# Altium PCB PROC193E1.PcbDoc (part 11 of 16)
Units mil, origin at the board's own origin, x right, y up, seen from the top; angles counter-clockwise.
Board outline 7700 x 2300 mil, 6 copper layers (Top Layer, GND 1, SIG 1, PWR, GND 2, Bottom Layer), stack 60.98 mil thick; 946 components, 667 nets, 9401 pads, 1730 vias.
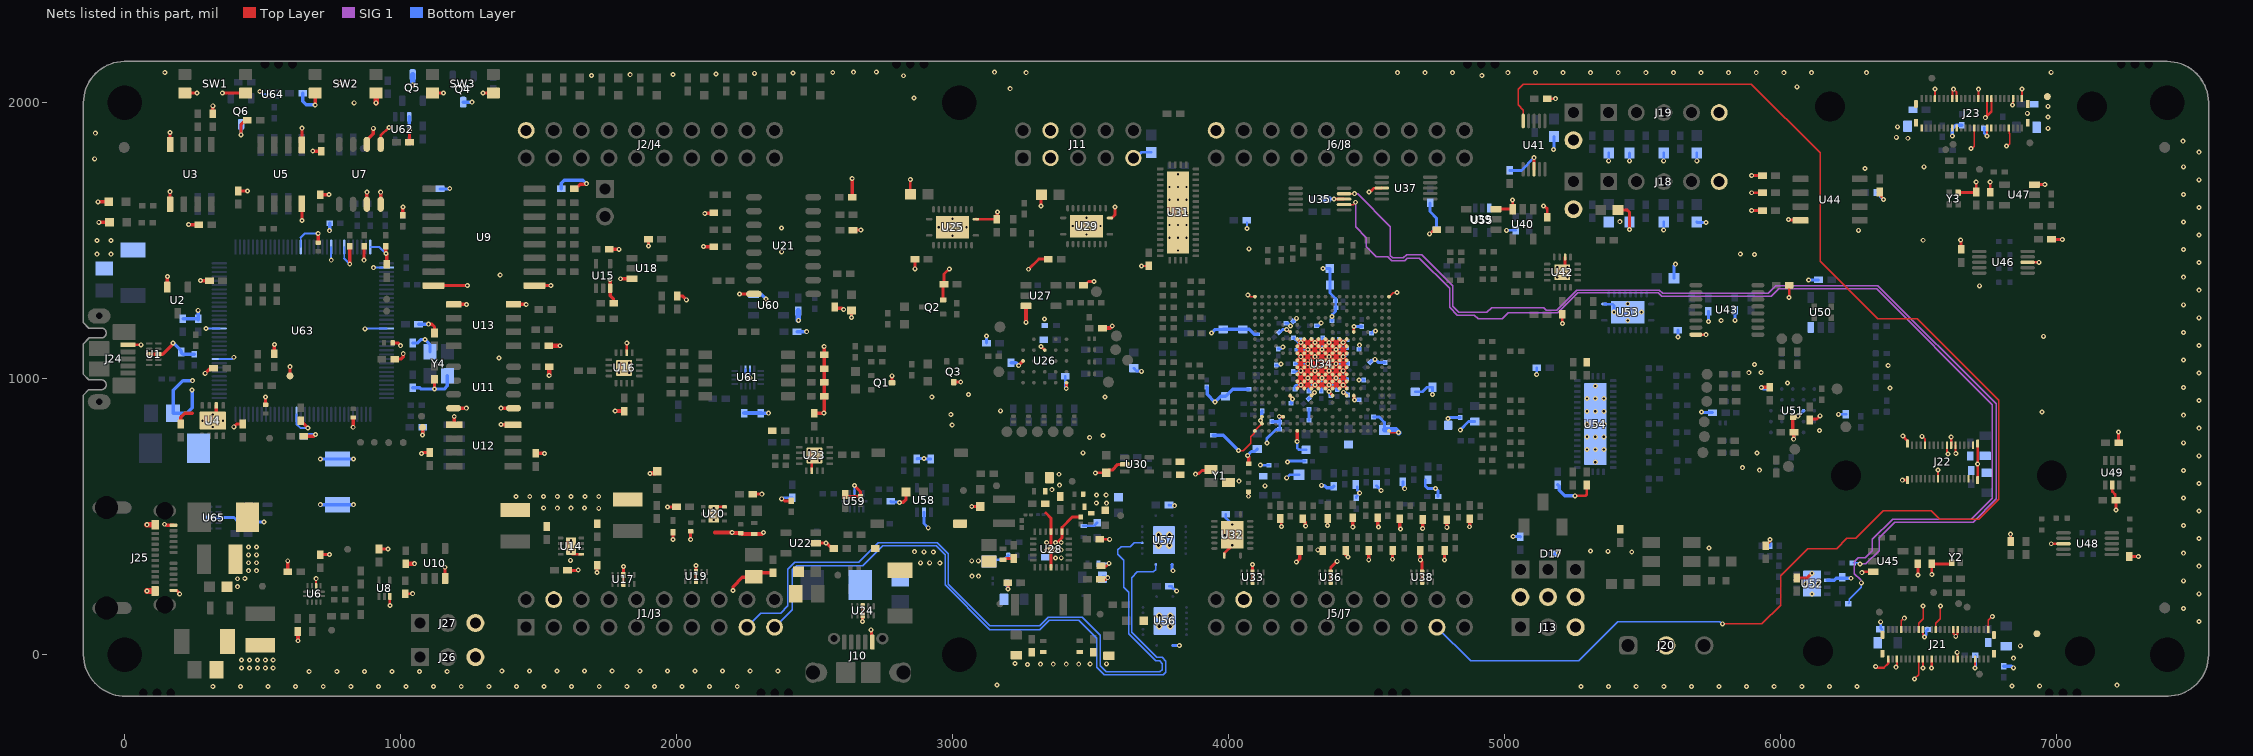
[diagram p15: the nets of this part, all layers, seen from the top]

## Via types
v1: diameter 18, hole 8, Top Layer to Bottom Layer, tented both sides, 1710 vias
v2: diameter 18, hole 8, Top Layer to Bottom Layer, tented top, 12 vias
v3: diameter 23.62, hole 11.81, Top Layer to Bottom Layer, tented both sides, 8 vias

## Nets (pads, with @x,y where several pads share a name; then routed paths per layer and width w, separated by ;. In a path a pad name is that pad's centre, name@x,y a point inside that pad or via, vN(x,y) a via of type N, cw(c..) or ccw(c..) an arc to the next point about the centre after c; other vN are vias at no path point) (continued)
GND: C1.1 C4.2 C5.2 C8.1 C11.2 C12.2 C15.2 C20.2 C22.2 C26.1 C27.2 C31.2 C32.1 C33.1 C34.2 C35.2 C36.2 C37.1 C38.2 C39.2 C40.2 C41.2 C42.1 C43.1 C44.2 C45.1 C46.1 C47.2 C48.2 C49.1 C50.2 C51.2 C52.2 C53.2 C54.1 C55.1 C56.2 C57.1 C58.2 C59.1 C60.2 C61.2 C62.2 C63.2 C64.2 C66.2 C67.2 C68.2 C69.2 C70.2 C71.2 C72.1 C73.2 C74.2 C75.2 C76.2 C77.2 C78.2 C79.2 C80.2 C81.2 C82.2 C83.2 C84.1 C85.2 C86.1 C87.2 C88.1 C89.1 C90.1 C91.1 C92.1 C93.1 C94.1 C95.1 C96.1 C97.1 C98.1 C99.1 C100.1 C101.1 C102.1 C103.1 C104.1 C105.1 C106.1 C107.1 C108.1 C109.2 C110.2 C112.2 C114.2 C115.2 C116.1 C117.2 C118.2 C119.1 C120.2 C121.1 C122.2 C123.2 C124.1 C125.2 C126.2 C127.2 C128.1 C129.1 C130.2 C131.2 C132.2 C133.2 C134.2 C135.2 C136.2 C137.2 C138.2 C139.2 C140.2 C141.2 C142.1 C143.2 C144.2 C145.2 C146.1 C147.2 C148.2 C149.2 C150.2 C151.2 C152.2 C153.2 C154.2 C155.2 C156.2 C157.2 C158.1 C159.2 C160.1 C161.1 C162.1 C163.1 C164.1 C165.1 C167.1 C168.2 C169.2 C170.1 C171.2 C172.2 C173.2 C174.2 C175.2 C176.2 C177.2 C178.1 C179.2 C180.1 C181.1 C182.1 C183.1 C184.1 C185.1 C186.2 C187.1 C188.1 C189.1 C190.2 C191.2 C192.2 C193.2 C194.1 C195.1 C196.1 C197.2 C198.1 C200.2 C201.2 C202.2 C203.2 C204.2 C205.2 C206.1 C207.2 C208.1 C209.2 C210.2 C211.2 C212.1 C213.2 C214.2 C215.2 C216.2 C217.1 C218.2 C219.2 C220.2 C221.2 C222.2 C223.2 C224.2 C225.2 C226.2 C227.2 C228.1 C229.1 C230.2 C231.1 C232.1 C233.1 C234.1 C235.1 C236.2 C237.2 C238.1 C239.2 C240.1 C241.1 C242.2 C243.1 C244.2 C245.2 C246.2 C247.2 C248.2 C249.2 C250.2 C251.2 C252.2 C253.2 C254.2 C255.2 C256.1 C257.1 C258.1 C264.2 C266.1 D2.1 D7.1 D12.1 D14.1 D15.1 D16.1 D17.2 D18.1 J1/J3.22 J2/J4.20 J5/J7.62 J6/J8.60 J10.5 J11.3 J11.4 J11.9 J12.2 J13.3 J14.2 J15.2 J16.2 J17.2 J18.5 J19.5 J20.2 J21.1 J21.5 J21.8 J21.15 J21.16 J21.17 J21.18 J21.21 J21.24 J21.31 J21.32 J21.33 J21.34 J21.41 J21.49 J21.50 J21.51 J21.52 J22.1 J22.4 J22.9 J22.11 J22.13 J22.18 J22.23 J22.31 J22.32 J22.33 J22.34 J23.1 J23.5 J23.8 J23.15 J23.16 J23.17 J23.18 J23.21 J23.24 J23.31 J23.32 J23.33 J23.34 J23.41 J23.49 J23.50 J23.51 J23.52 J25.A1 J25.A12 J25.B1 J25.B12 J26.3 J27.3 Q1.3 Q2.2 Q3.3 Q4.3 Q5.3 Q6.3 R3.2 R13.1 R15.1 R25.2 R31.2 R50.1 R51.2 R53.1 R55.1 R60.1 R63.2 R66.2 R68.1 R69.1 R70.1 R71.1 R72.2 R74.1 R75.1 R80.2 R85.1 R88.1 R90.2 R101.1 R121.1 R189.2 R190.2 R195.1 R200.1 R201.1 R202.1 R216.2 R218.2 R231.2 R233.1 R235.2 R236.2 R239.1 R246.2 R253.1 R264.1 R267.2 R274.2 R302.2 R303.2 R308.1 R314.1 R319.1 R323.1 R351.1 R352.2 R354.2 R362.1 R363.2 R374.1 SW1.1 SW1.3 SW2.1 SW2.3 SW3.1 SW3.3 SW5.2 TP55.1 TP56.1 U3.4 U5.5 U6.10 U7.5 U7.6 U8.3 U9.9 U10.3 U11.5 U12.4 U13.4 U14.5 U14.9 U15.3 U16.6 U16.17@1809.13,1039.54 U17.3@1806.54,256.9 U17.8@1806.54,289.78 U18.3 U19.3@2069.81,267.45 U19.8@2069.81,300.32 U20.3 U20.7@2134.1,510.44 U21.16 U22.2 U23.6 U23.17@2498.69,722.15 U24.3@2674,142.95 U24.8@2674,175.83 U25.11 U25.21 U26.B3 U26.C1 U26.E5 U27.3 U28. U28.2 U28.4 U28.16 U29.11 U29.21 U30.2 U31.43 U32.8 U32.17 U33.3@4085.92,264.9 U33.8@4085.92,297.78 U34.A1 U34.A20 U34.F6 U34.F15 U34.G7 U34.G8 U34.G9 U34.G10 U34.G11 U34.G12 U34.G13 U34.G14 U34.H7 U34.H8 U34.H9 U34.H10 U34.H11 U34.H12 U34.H13 U34.H14 U34.J7 U34.J8 U34.J9 U34.J10 U34.J11 U34.J12 U34.J13 U34.J14 U34.K7 U34.K8 U34.K9 U34.K10 U34.K11 U34.K12 U34.K13 U34.K14 U34.L7 U34.L8 U34.L9 U34.L10 U34.L11 U34.L12 U34.L13 U34.L14 U34.M7 U34.M8 U34.M9 U34.M10 U34.M11 U34.M12 U34.M13 U34.M14 U34.N7 U34.N8 U34.N9 U34.N10 U34.N11 U34.N12 U34.N13 U34.N14 U34.P7 U34.P8 U34.P9 U34.P10 U34.P11 U34.P12 U34.P13 U34.P14 U34.R6 U34.R9 U34.R12 U34.R14 U34.R15 U34.V2 U34.V5 U34.W2 U34.Y1 U34.Y7 U34.Y20 U35.3 U36.3@4369.09,297.78 U36.8@4369.09,264.9 U37.3 U38.3@4700.31,297.78 U38.8@4700.31,264.9 U39.3 U40.3 U41.3 U42.6 U42.17@5208.52,1386.21 U43.8 U44.4 U45.3 U46.3 U47.3 U48.3 U49.2 U50.3 U51.B3 U51.C1 U51.E5 U52.2 U52.9 U53.11 U53.21 U54.43 U55.3 U56.8 U56.17 U57.8 U57.17 U58.2 U59.9 U60.3 U61.10 U61.11 U62.3 U64.2 U65.3@306.02,497.27 U65.8@338.89,497.27 Y1.2 Y1.4 Y2.2 Y3.2 | length 19237.5
  Top Layer w5.3: v1(4035.17,739.99) 4052.27,739.99 4079.46,767.19 4079.46,789.53 4092.86,802.93 4092.86,809.76 U34.Y1@4094.49,811.38 U34.W2@4120.08,836.97 ; v1(4068.86,1303.93) 4072.29,1303.93 4078.62,1297.6 U34.A1@4094.49,1297.6 ; v1(4114.93,849.12) 4120.08,854.27 U34.V2@4120.08,862.57 ; v1@4415.65,950.85 v1(4415.65,951.09) ; U34.Y20@4580.71,811.38 4587.03,805.06 v1(4615.01,805.06) ; U34.A20@4580.71,1297.6 4595.69,1312.59 v1(4609.23,1312.59) ; J21.8@6436.31,91.39 6436.31,124.21 6444.68,132.59 v1(6447.51,132.59) ; v1@6483.89,-87.09 6499.3,-71.68 J21.15@6499.3,-15.3 ; J21.16@6499.3,91.39 6499.3,114.06 6515.41,130.17 v1(6515.41,176.47) ; J21.24@6562.29,91.39 6561.76,91.92 6561.76,114.13 6578.41,130.77 v1(6578.41,176.47) ; v1@6691.78,1834 6700.18,1842.4 J23.24@6700.18,1908.44 ; v1(6818,1843) 6820.55,1843 6829.07,1851.51 6829.07,1887.65 6826.86,1889.85 6826.86,1898.1 6826.17,1898.8 J23.8@6826.17,1908.44
  Top Layer w7: U6.10@693.44,250.21 v1(693.44,275.6) ; v1(6512.08,791.6) 6522.89,780.79 J22.23@6522.89,759.66 ; J22.18@6570.14,638.4 v1@6570.14,669.39 ; J22.13@6601.63,759.66 6601.63,734.57 6605.57,730.64 v1(6605.57,727.93) ; v1(6625.22,2049.35) 6637.19,2037.37 J23.31@6637.19,2015.13 ; J22.9@6633.13,759.66 6633.13,730.31 v1(6633.94,729.5)
  Top Layer w8: U16.6@1818.97,1094.65 v1(1818.97,1129.8) ; v1(2479.99,703.45) 2483.01,703.45 2488.85,697.61 U23.6@2488.85,667.03 ; v1(3683.7,1408.2) 3708.05,1408.2 C86.1@3709.11,1409.27 ; v1@4071.45,574.51 C88.1@4071.47,591.21 ; v1(6343.79,-42.49) 6348.6,-47.3 6373.06,-47.3 6389.06,-31.3 J21.1@6389.06,-15.3 ; v1(6417.83,-45.04) 6420.56,-42.31 J21.5@6420.56,-15.3 ; v1(6514.71,-47.64) 6515.05,-47.3 J21.17@6515.05,-15.3 ; J21.18@6515.05,91.39 6515.57,90.87 6515.57,73.18 6521.05,67.71 v1(6521.05,65) ; v1(6546.21,-47.64) 6546.54,-47.3 J21.21@6546.54,-15.3 ; J23.41@6558.45,2015.13 v1(6558.45,2049.91) ; J22.11@6617.38,759.66 v1(6617.38,788.61) ; J23.33@6621.44,2015.13 6621.44,2023.95 6621.62,2024.13 6621.62,2043.04 6623.3,2044.73 6623.3,2047.43 v1(6625.22,2049.35) ; J21.32@6625.28,91.39 6625.81,90.87 6625.81,76.58 v1@6633.88,68.51 ; v1(6633.88,66.89) v1@6633.88,68.51 ; v1(6639.05,9) 6640.5,7.55 6640.5,-14.77 J21.33@6641.03,-15.3 ; J21.34@6641.03,91.39 6640.5,90.87 6640.5,76.22 6633.88,69.6 v1@6633.88,68.51 ; v1(6703.69,-47.64) 6704.02,-47.3 J21.41@6704.02,-15.3 ; J23.21@6715.93,2015.13 v1(6715.93,2049.35) ; v1(6741,1946) v1@6746.91,1951.91 ; v1(6747.43,1879.92) J23.18@6747.43,1908.44 ; J23.17@6747.43,2015.13 6747.43,1960.13 6746.91,1959.62 v1@6746.91,1951.91 ; J23.15@6763.17,2015.13 6763.17,1968.17 v1@6746.91,1951.91 ; v1(6839.9,1992.32) 6841.39,1993.8 6841.39,2014.61 J23.5@6841.91,2015.13 ; J23.1@6873.41,2015.13 v1@6873.41,2050.04
  Top Layer w10: U7.5@927.09,1849.31 927.09,1881.02 v1(956.83,1910.76) ; v1@960.35,178.54 U8.3@960.35,211.46 ; R25.2@1016.9,221.53 v1(1043.03,221.53) ; C26.1@1031.48,1856.71 1031.48,1900.04 v1(1032.23,1900.79) ; U10.3@1160.43,276.85 v1(1160.43,317.22) ; R31.2@1603.84,305.62 1639,305.62 1640.73,307.35 v1(1642.89,307.35) ; v1(1616.72,372.03) 1616.72,370.06 1622.62,364.15 U14.5@1654.12,364.15 ; U14.9@1616.72,393.68 1616.72,379.9 U14.9@1620.65,375.96 ; v1(1710.81,297.92) 1711.09,298.19 1711.09,323.87 C38.2@1711.37,324.15 ; U17.3@1806.54,256.9 U17.8@1806.54,289.78 v1(1806.54,319.63) ; U19.3@2069.81,267.45 U19.8@2069.81,300.32 2069.81,323.38 v1(2070.03,323.6) ; v1(2134.1,532.09) 2138.04,536.03 U20.3@2172.49,536.03 ; v1(2703.14,90.7) 2703.14,88.53 2705.58,86.1 2705.58,49.04 J10.5@2708.45,46.17 ; Q1.3@2779.73,985.75 v1(2779.73,1010.72) ; v1(2846.02,1722.5) 2846.02,1669.97 C58.2@2847.31,1668.67 ; C59.1@2862.89,1433.48 2863.13,1433.24 v1(2863.13,1398.63) ; Q2.2@2964.69,1285.58 2964.69,1338.47 R85.1@2968.27,1342.04 2968.27,1379.35 v1(2987.21,1398.28) ; Q3.3@3003.55,988.08 v1(3028.84,988.08) ; v1(3068.61,537.33) 3099.75,537.33 D14.1@3099.79,537.37 ; U25.11@3083.62,1578.6 3145.94,1578.29 3153.27,1578.29 R90.2@3160.08,1578.29 ; C61.2@3181.83,344.4 3186.33,344.4 3191.19,349.25 C63.2@3221.59,349.25 ; C62.2@3199.08,261.73 3199.57,261.24 v1(3199.57,238.84) ; v1(3238.72,1048.62) v1@3238.72,1048.71 ; U26.C1@3254.52,1064.51 U26.C1@3254.52,1064.6 ; v1(3274.71,1396.93) 3311.69,1433.91 C72.1@3346.13,1433.91 ; v1(3319.1,1626.17) 3319.1,1649.1 C70.2@3321.87,1651.87 ; v1@3319.94,1117.29 U26.B3@3333.26,1103.97 ; 3336.99,513.65 3355.95,494.68 U28.4@3355.95,446.5 3355.95,395.5 3355.83,395.38 ; 3355.83,364.78 3355.95,364.65 U28.16@3355.95,316.58 ; 3382.55,411.3 3395.32,424.07 U28.2@3395.32,446.5 3395.32,461.93 3432.91,499.52 C78.2@3463.78,499.52 ; C74.2@3473.85,1338.74 3477.86,1338.74 3491.45,1352.33 v1(3511.18,1352.33) ; v1(3516.4,658.87) 3517.07,659.54 D15.1@3555.43,659.54 ; C79.2@3532.55,418.56 v1(3568.29,418.56) ; C80.2@3534.98,273.17 3555.04,273.17 v1(3561.2,279.33) ; C81.2@3536.64,321.86 3556.21,321.86 v1(3565.84,331.49) ; U29.11@3576.11,1583 3587.4,1594.29 v1(3587.4,1622.59) ; v1(3879.72,654.32) 3881.25,655.85 3890.86,655.85 3902.57,667.57 3931.23,667.57 Y1.2@3935.33,671.68 ; U32.8@3983.28,359.69 3983.28,367.56 v1(4012.8,397.09) ; U33.3@4085.92,264.9 U33.8@4085.92,297.78 v1(4085.92,326.83) ; C90.1@4186.24,493.49 4189.63,490.1 4189.63,466.52 v1(4191.16,464.99) ; v1(4209.64,1178.48) 4211.8,1178.48 4219.91,1170.38 4221.71,1170.38 U34.F6@4222.44,1169.65 ; U34.R9@4299.21,939.34 4310.73,950.85 v1(4310.96,950.85) ; v1(4363.19,954.32) 4363.19,953.15 4375.98,940.36 U34.R12@4375.98,939.34 ; U36.8@4369.09,264.9 U36.3@4369.09,297.78 4369.09,315.39 v1(4392.59,338.88) ; v1(4381.29,1650.98) U35.3@4417.57,1651.01 ; v1@4415.65,950.85 U34.R14@4427.16,939.34 ; U34.R15@4452.75,939.34 4453.48,938.61 4453.48,927.31 4455.5,925.28 v1(4455.5,923.12) ; U34.F15@4452.75,1169.65 4452.75,1188.17 v1(4454.04,1189.46) ; v1(4508.02,1677.13) 4510.18,1677.13 4514.18,1681.13 4516.02,1681.13 4525.62,1690.74 4553.92,1690.74 U37.3@4554.27,1691.08 ; v1(4693.83,344.15) 4700.31,337.67 U38.3@4700.31,297.78 U38.8@4700.31,264.9 ; v1(4726.83,1525.28) 4728.43,1525.28 4736.68,1533.53 4746.47,1533.53 C103.1@4753.28,1540.34 ; U39.3@4968.56,1615.04 5027.59,1615.04 U40.3@5028.41,1614.21 v1(5028.41,1647.88) ; U41.3@5105.92,1759.01 v1(5105.92,1801.13) ; v1(5140.11,1626.37) 5141.64,1624.84 5145.02,1624.84 5153.78,1616.07 C108.1@5153.78,1585.32 ; C107.1@5153.89,2014.55 5182.88,2014.55 v1(5183.28,2014.94) ; C109.2@5208.02,1234.24 5208.02,1200.59 v1(5208.53,1200.08) ; U42.6@5218.36,1441.33 5218.36,1409.76 5223.2,1404.91 v1(5227.22,1404.91) ; v1(5254,576) 5291.43,576 5297.29,581.86 R189.2@5297.29,615.2 ; U43.8@5692.24,1159.93 v1(5728.81,1159.93) ; v1(5894.5,1609.69) 5894.64,1609.55 5933.69,1609.55 R201.1@5933.83,1609.41 ; v1(5894.5,1674.05) R202.1@5933.83,1674.05 ; v1(5894.5,1736.2) R200.1@5933.83,1736.2 ; C114.2@5944.74,394.99 5960.46,410.7 v1(5960.46,418.23) ; v1(6028.19,1577.21) 6029.72,1575.68 6069.54,1575.68 U44.4@6071.17,1574.05 ; v1(6029.56,1294.76) 6030.37,1295.58 C116.1@6030.37,1338.39 ; C117.2@6044.87,808.46 C117.2@6047.48,805.84 ; C120.2@6104.06,850.93 6107.81,854.68 6130.92,854.68 v1(6142.2,865.96) ; v1(6293.61,297.39) 6295.78,297.39 6299.17,300.79 U45.3@6334.74,300.79 ; C121.1@6357.97,1676.78 6364.78,1669.97 6364.78,1658.93 6371.94,1651.76 v1(6371.94,1649.6) ; v1(6440.36,632.65) 6440.59,632.89 J22.32@6458.33,632.89 ; v1(6442.1,792.77) 6457.81,777.06 6457.81,765.69 J22.34@6458.33,765.17 ; v1(6496.77,289.56) C122.2@6496.77,329.4 ; v1(6547.26,290.98) C123.2@6547.26,329.4 6616.11,329.4 Y2.2@6619.35,332.64 ; Y3.2@6642.15,1674.86 6706.08,1674.86 C125.2@6708.05,1676.83 6708.05,1713.44 v1(6707.93,1713.56) ; v1(6651.86,1503.22) 6653.11,1501.96 6653.11,1470.2 C124.1@6654.37,1468.94 ; J22.31@6713.44,632.89 6713.44,691.36 v1(6713.26,691.55) 6713.44,691.73 J22.33@6713.44,765.17 ; C126.2@6758.52,1676.03 v1(6758.52,1713.44) ; v1(6832.64,436.83) 6832.94,436.53 6832.94,410.94 R216.2@6833.24,410.64 ; v1@6873.41,2050.04 v1(6873.87,2050.5) ; U46.3@6894.37,1422.22 v1(6935.36,1422.22) ; U47.3@6918.86,1703.75 v1(6956.66,1703.75) ; v1(6979.88,402.4) 7024.02,402.4 U48.3@7024.14,402.52 ; R218.2@6980.88,1504.96 7019.69,1504.96 v1(7019.86,1504.79) ; U49.2@7200.68,615.29 7201.15,614.82 7201.15,591.09 7211.51,580.73 7211.51,562.53 C127.2@7214.27,559.77 v1(7214.27,524.94) ; C128.1@7223.93,768.73 v1@7223.93,807.32 ; C129.1@7263.05,356.45 v1@7295.17,356.45
  Top Layer w11: v1(144,473) 145.89,473 149.53,469.37 J25.A1@176.63,469.37 ; J25.A12@176.63,233.15 177.04,232.74 188.21,232.74 198.93,222.02 v1(198.93,220.48) ; v1(1965.79,536.03) R50.1@1998.71,536.03 ; v1(1986.19,417.66) C44.2@1986.19,443.3 ; v1(2050.18,417.66) C45.1@2050.18,447.54 ; R60.1@2274.63,582.06 v1(2308.09,582.06) ; v1(2380.17,565.14) 2382,565.14 2389.85,557.29 R66.2@2415.21,557.29 ; U22.2@2505.4,405.42 v1(2541.01,405.42) ; C54.1@2610.25,580.89 2610.25,580.31 2616.56,574 C56.2@2665.63,574 ; v1@2643.87,612.87 2665.63,591.12 C56.2@2665.63,574.24 ; v1(2673.3,120.95) 2673.65,121.3 2673.65,142.6 U24.3@2674,142.95
  Top Layer w12: v1(163.9,1892.59) 164.01,1892.48 U3.4@164.01,1849.08 ; SW1.1@217.32,2035.35 v1(261.88,2035.35) ; C8.1@318.73,1960.51 v1(318.73,1989.01) ; v1(353.19,2035.93) 353.76,2035.35 SW1.3@437.8,2035.35 ; v1(421.14,1884.01) 421.14,1921.76 430.46,1931.08 437.61,1931.08 C11.2@443.42,1936.89 ; C15.2@590.41,301.51 v1(590.41,340.66) ; v1(641.56,1907.98) 641.82,1907.72 U5.5@641.82,1847.11 ; v1(680.93,1825.27) 681.68,1824.52 C20.2@711.42,1824.52 ; v1(689.76,1992.44) SW2.1@689.76,2035.35 ; R15.1@708.66,362.63 709.13,363.1 v1(741.85,363.15) v1(741.85,363.15) ; U7.6@877.09,1849.31 877.09,1865 900.47,1888.39 v1(900.47,1907.56) ; C22.2@921.05,383.51 v1(953.18,383.51) ; SW3.1@1114.76,2035.35 v1(1154.29,2035.35) ; v1(1298.34,2035.23) 1298.46,2035.35 SW3.3@1335.24,2035.35 ; v1(1363.22,834.47) 1363.95,833.75 1405.58,833.75 U12.4@1406.3,833.03 ; v1(1363.22,893.59) U11.5@1408.5,893.59 ; U13.4@1408.27,1269.73 v1(1454.17,1269.73) ; U9.9@1484.79,1337.95 v1(1543.62,1337.95) ; C34.2@1489.23,729.75 v1(1520.75,729.75) ; C36.2@1628.41,1687.95 1632.35,1687.95 1649.63,1705.24 1669.61,1705.24 1671.38,1707 v1(1673,1707) ; C37.1@1755.35,1469.23 v1(1790.8,1469.23) ; v1(1758.55,1360.32) U15.3@1758.55,1328.23 1758.55,1301.46 1770.42,1289.59 1770.42,1273.35 C40.2@1771.58,1273.35 ; v1(1796.54,1362.48) U18.3@1837.83,1362.48 ; C43.1@1896.45,1506.14 C43.1@1897.51,1505.08 v1(1897.51,1481.55) ; R51.2@2001.1,1300.24 2020.18,1300.24 v1(2034.38,1286.04) ; v1(2096.84,1478.99) R53.1@2134.14,1478.99 ; v1(2101.49,1598.74) 2102.64,1599.89 2131.75,1599.89 R55.1@2134.14,1602.28 ; v1(2203.89,232.77) 2203.89,247.41 2236.96,280.48 2277.22,280.48 C47.2@2279.43,282.68 2294.21,297.46 C49.1@2348.53,297.46 ; v1(2227.27,1307.42) U21.16@2279.55,1307.42 ; C52.2@2497.29,875.33 2532.29,875.33 v1(2532.68,875.72) 2532.68,877.35 2534.55,879.22 R68.1@2534.55,936.88 R69.1@2534.55,986.88 R70.1@2534.55,1036.88 R71.1@2534.55,1086.88 2534.55,1116.45 v1(2534,1117) ; v1(2541.01,405.42) 2555.51,390.92 2562.95,390.92 R72.2@2568.77,385.11 ; C53.2@2572.78,1260.18 2577.13,1255.83 2598.18,1255.83 2603.12,1250.89 v1(2604.74,1250.89) ; v1(2632.78,1221.86) C55.1@2632.78,1247.58 ; R74.1@2635.46,1657.42 v1(2635.46,1725.83) ; R75.1@2638.47,1538.98 2638.68,1539.2 2666.43,1539.2 v1(2666.65,1539.42) ; U24.3@2674,142.95 U24.8@2674,175.83 ; v1(2806.96,552.14) 2807.92,553.1 2820.19,553.1 2830.51,563.43 2830.51,589.98 D12.1@2830.67,590.14 ; R90.2@3160.08,1578.29 3160.76,1578.97 3160.76,1603.65 v1(3161.44,1604.32) ; v1@3238.72,1048.71 U26.C1@3254.52,1064.51 ; v1(3411.07,964.88) 3412,965.81 U26.E5@3412,985.86 ; D15.1@3555.43,659.54 3565.18,669.29 3578.08,669.29 3598.38,689.59 3622.85,689.59 U30.2@3623.07,689.8 ; v1(4068.6,722.43) 4068.6,720.81 4072,717.4 4072,692.49 C89.1@4072.36,692.13 ; v1(4182.82,862.93) 4183.18,862.57 U34.V5@4196.85,862.57 ; U34.R6@4222.44,939.34 4222.78,939 4222.78,936.83 4231.18,928.43 v1(4231.18,926.81) ; v1(4244.5,335.98) 4256.83,348.31 4256.83,377.41 C91.1@4257.17,377.75 ; v1(4247.81,772.59) 4248.03,772.81 U34.Y7@4248.03,811.38 ; U34.P7@4248.03,964.93 v2(4260.82,977.72) ; U34.G7@4248.03,1144.06 v2(4260.82,1131.27) ; C92.1@4268.54,492.59 4268.54,488.65 4277.39,479.8 4277.39,468.08 v1(4278.54,466.94) ; v1(4322.65,380.25) 4323.79,379.1 4339.76,379.1 C93.1@4339.84,379.18 ; C94.1@4357.2,493.29 4357.72,492.76 v1(4357.72,468.74) ; C95.1@4424.28,377.75 4424.28,362.36 v1(4431.86,354.78) ; U34.P14@4427.16,964.93 v2(4414.37,977.72) ; U34.G14@4427.16,1144.06 v2(4414.37,1131.27) ; v1(4449.31,462.92) 4449.49,463.1 C96.1@4449.49,496.51 ; v1(4507.01,344.15) 4507.2,344.34 C97.1@4507.2,377.75 ; C98.1@4539.23,496.09 4539.69,495.63 4539.69,466.76 4542.05,464.4 v1(4542.05,462.78) ; C99.1@4593.17,377.75 4593.33,368 v1(4593.33,346.2) ; C100.1@4619.66,492.46 4619.66,459.98 4622.48,457.16 v1(4622.48,455.54) ; C100.1@4622.57,492.37 C100.1@4622.66,492.46 ; v1(4693.83,344.15) 4694.01,344.34 C101.1@4694.01,377.75 ; v1(4702.6,457.77) v1(4702.6,457.77) 4702.65,490.22 C102.1@4702.69,490.26 ; v1(4781.56,343.91) C104.1@4781.56,377.75 ; v1(4789.92,461.94) 4790.1,462.13 C105.1@4790.1,489.2 ; v1(4872,464) 4872.63,464.63 4872.63,492.73 C106.1@4873.26,493.36 ; C110.2@5410.43,1611.36 5444.49,1611.36 5451.52,1604.33 v1(5451.52,1540.83) ; v1(5929.42,968.97) C115.2@5959.69,968.97 ; C117.2@6044.87,808.46 6043.54,809.78 6043.54,859.97 C118.2@6044.87,861.29 ; v1(6046.78,781.31) 6047.13,781.66 6047.13,805.5 C117.2@6047.48,805.84 ; C119.1@6057.28,278.46 6096.45,278.46 v1(6113.11,295.11) ; v2(4260.82,977.72) U34.N8@4273.62,990.52 ; v2(4260.82,977.72) U34.P8@4273.62,964.93 4286.41,977.72 ; v2(4260.82,977.72) U34.N7@4248.03,990.52 4260.82,1003.31 ; 4260.82,1003.31 U34.N8@4273.62,990.52 ; 4260.82,1003.31 U34.M8@4273.62,1016.11 ; 4260.82,1003.31 U34.M7@4248.03,1016.11 v2(4260.82,1028.9) ; v2(4260.82,1028.9) U34.L8@4273.62,1041.7 ; v2(4260.82,1028.9) U34.L7@4248.03,1041.7 4260.82,1054.5 ; v2(4260.82,1028.9) U34.M8@4273.62,1016.11 ; 4260.82,1054.5 U34.K8@4273.62,1067.29 ; 4260.82,1054.49 U34.L8@4273.62,1041.7 ; 4260.82,1054.5 U34.K7@4248.03,1067.29 v2(4260.82,1080.09) ; v2(4260.82,1080.09) U34.K8@4273.62,1067.29 ; v2(4260.82,1080.09) U34.J8@4273.62,1092.88 ; v2(4260.82,1080.09) U34.J7@4248.03,1092.88 4260.82,1105.68 ; 4260.82,1105.68 U34.H8@4273.62,1118.47 ; 4260.82,1105.68 U34.H7@4248.03,1118.47 v2(4260.82,1131.27) ; 4260.82,1105.68 U34.J8@4273.62,1092.88 ; v2(4260.82,1131.27) U34.G8@4273.62,1144.06 4286.41,1131.27 ; v2(4260.82,1131.27) U34.H8@4273.62,1118.47 ; U34.N8@4273.62,990.52 v1(4286.41,1003.31) ; U34.N8@4273.62,990.52 4286.41,977.72 ; U34.M8@4273.62,1016.11 v1(4286.41,1003.31) ; U34.M8@4273.62,1016.11 4286.41,1028.9 ; U34.L8@4273.62,1041.7 v1(4286.41,1054.49) ; U34.L8@4273.62,1041.7 4286.41,1028.9 ; U34.K8@4273.62,1067.29 4286.41,1080.09 ; U34.K8@4273.62,1067.29 v1(4286.41,1054.49) ; U34.J8@4273.62,1092.88 v1(4286.41,1105.68) ; U34.J8@4273.62,1092.88 4286.41,1080.09 ; U34.H8@4273.62,1118.47 4286.41,1131.27 ; U34.H8@4273.62,1118.47 v1(4286.41,1105.68) ; 4286.41,977.72 U34.N9@4299.21,990.52 ; 4286.41,977.72 U34.P9@4299.21,964.93 v2(4312.01,977.72) ; v1(4286.41,1003.31) U34.N9@4299.21,990.52 ; v1(4286.41,1003.31) U34.M9@4299.21,1016.11 ; 4286.41,1028.9 U34.L9@4299.21,1041.7 ; 4286.41,1028.9 U34.M9@4299.21,1016.11 ; v1(4286.41,1054.49) U34.L9@4299.21,1041.7 ; v1(4286.41,1054.49) U34.K9@4299.21,1067.29 ; 4286.41,1080.09 U34.J9@4299.21,1092.88 ; 4286.41,1080.09 U34.K9@4299.21,1067.29 ; v1(4286.41,1105.68) U34.H9@4299.21,1118.47 ; v1(4286.41,1105.68) U34.J9@4299.21,1092.88 ; 4286.41,1131.27 U34.G9@4299.21,1144.06 v2(4312.01,1131.27) ; 4286.41,1131.27 U34.H9@4299.21,1118.47 ; U34.N9@4299.21,990.52 4312.01,1003.31 ; U34.N9@4299.21,990.52 v2(4312.01,977.72) ; U34.M9@4299.21,1016.11 4312.01,1003.31 ; U34.M9@4299.21,1016.11 v1(4312.01,1028.9) ; U34.L9@4299.21,1041.7 4312.01,1054.5 ; U34.L9@4299.21,1041.7 v1(4312.01,1028.9) ; U34.K9@4299.21,1067.29 v1(4312.01,1080.09) ; U34.K9@4299.21,1067.29 4312.01,1054.5 ; U34.J9@4299.21,1092.88 v1(4312.01,1080.09) ; U34.J9@4299.21,1092.88 4312.01,1105.68 ; U34.H9@4299.21,1118.47 v2(4312.01,1131.27) ; U34.H9@4299.21,1118.47 4312.01,1105.68 ; v2(4312.01,977.72) U34.N10@4324.8,990.52 ; v2(4312.01,977.72) U34.P10@4324.8,964.93 4337.6,977.72 ; 4312.01,1003.31 U34.M10@4324.8,1016.11 ; 4312.01,1003.31 U34.N10@4324.8,990.52 ; v1(4312.01,1028.9) U34.L10@4324.8,1041.7 ; v1(4312.01,1028.9) U34.M10@4324.8,1016.11 ; 4312.01,1054.5 U34.K10@4324.8,1067.29 ; 4312.01,1054.49 U34.L10@4324.8,1041.7 ; v1(4312.01,1080.09) U34.J10@4324.8,1092.88 ; v1(4312.01,1080.09) U34.K10@4324.8,1067.29 ; 4312.01,1105.68 U34.H10@4324.8,1118.47 ; 4312.01,1105.68 U34.J10@4324.8,1092.88 ; v2(4312.01,1131.27) U34.G10@4324.8,1144.06 4337.6,1131.27 ; v2(4312.01,1131.27) U34.H10@4324.8,1118.47 ; U34.N10@4324.8,990.52 v1(4337.6,1003.31) ; U34.N10@4324.8,990.52 4337.6,977.72 ; U34.M10@4324.8,1016.11 v1(4337.6,1003.31) ; U34.M10@4324.8,1016.11 4337.6,1028.9 ; U34.L10@4324.8,1041.7 v1(4337.6,1054.49) ; U34.L10@4324.8,1041.7 4337.6,1028.9 ; U34.K10@4324.8,1067.29 4337.6,1080.09 ; U34.K10@4324.8,1067.29 v1(4337.6,1054.49) ; U34.J10@4324.8,1092.88 4337.6,1080.09 ; U34.J10@4324.8,1092.88 v1(4337.6,1105.68) ; U34.H10@4324.8,1118.47 4337.6,1131.27 ; U34.H10@4324.8,1118.47 v1(4337.6,1105.68) ; 4337.6,977.72 U34.N11@4350.39,990.52 ; 4337.6,977.72 U34.P11@4350.39,964.93 v2(4363.19,977.72) ; v1(4337.6,1003.31) U34.M11@4350.39,1016.11 ; v1(4337.6,1003.31) U34.N11@4350.39,990.52 ; 4337.6,1028.9 U34.M11@4350.39,1016.11 ; 4337.6,1028.9 U34.L11@4350.39,1041.7 ; v1(4337.6,1054.49) U34.K11@4350.39,1067.29 ; v1(4337.6,1054.49) U34.L11@4350.39,1041.7 ; 4337.6,1080.09 U34.J11@4350.39,1092.88 ; 4337.6,1080.09 U34.K11@4350.39,1067.29 ; v1(4337.6,1105.68) U34.H11@4350.39,1118.47 ; v1(4337.6,1105.68) U34.J11@4350.39,1092.88 ; 4337.6,1131.27 U34.G11@4350.39,1144.06 v2(4363.19,1131.27) ; 4337.6,1131.27 U34.H11@4350.39,1118.47 ; U34.N11@4350.39,990.52 4363.19,1003.31 ; U34.N11@4350.39,990.52 v2(4363.19,977.72) ; U34.M11@4350.39,1016.11 v1(4363.19,1028.9) ; U34.M11@4350.39,1016.11 4363.19,1003.31 ; U34.L11@4350.39,1041.7 4363.19,1054.5 ; U34.L11@4350.39,1041.7 v1(4363.19,1028.9) ; U34.K11@4350.39,1067.29 v1(4363.19,1080.09) ; U34.K11@4350.39,1067.29 4363.19,1054.5 ; U34.J11@4350.39,1092.88 4363.19,1105.68 ; U34.J11@4350.39,1092.88 v1(4363.19,1080.09) ; U34.H11@4350.39,1118.47 v2(4363.19,1131.27) ; U34.H11@4350.39,1118.47 4363.19,1105.68 ; v2(4363.19,977.72) U34.N12@4375.98,990.52 ; v2(4363.19,977.72) U34.P12@4375.98,964.93 4388.78,977.72 ; 4363.19,1003.31 U34.M12@4375.98,1016.11 ; 4363.19,1003.31 U34.N12@4375.98,990.52 ; v1(4363.19,1028.9) U34.L12@4375.98,1041.7 ; v1(4363.19,1028.9) U34.M12@4375.98,1016.11 ; 4363.19,1054.5 U34.K12@4375.98,1067.29 ; 4363.19,1054.49 U34.L12@4375.98,1041.7 ; v1(4363.19,1080.09) U34.J12@4375.98,1092.88 ; v1(4363.19,1080.09) U34.K12@4375.98,1067.29 ; 4363.19,1105.68 U34.H12@4375.98,1118.47 ; 4363.19,1105.68 U34.J12@4375.98,1092.88 ; v2(4363.19,1131.27) U34.G12@4375.98,1144.06 4388.78,1131.27 ; v2(4363.19,1131.27) U34.H12@4375.98,1118.47 ; U34.N12@4375.98,990.52 v1(4388.78,1003.31) ; U34.N12@4375.98,990.52 4388.78,977.72 ; U34.M12@4375.98,1016.11 4388.78,1028.9 ; U34.M12@4375.98,1016.11 v1(4388.78,1003.31) ; U34.L12@4375.98,1041.7 v1(4388.78,1054.49) ; U34.L12@4375.98,1041.7 4388.78,1028.9 ; U34.K12@4375.98,1067.29 4388.78,1080.09 ; U34.K12@4375.98,1067.29 v1(4388.78,1054.49) ; U34.J12@4375.98,1092.88 v1(4388.78,1105.68) ; U34.J12@4375.98,1092.88 4388.78,1080.09 ; U34.H12@4375.98,1118.47 4388.78,1131.27 ; U34.H12@4375.98,1118.47 v1(4388.78,1105.68) ; 4388.78,977.72 U34.N13@4401.57,990.52 ; 4388.78,977.72 U34.P13@4401.57,964.93 v2(4414.37,977.72) ; v1(4388.78,1003.31) U34.M13@4401.57,1016.11 ; v1(4388.78,1003.31) U34.N13@4401.57,990.52 ; 4388.78,1028.9 U34.M13@4401.57,1016.11 ; 4388.78,1028.9 U34.L13@4401.57,1041.7 ; v1(4388.78,1054.49) U34.K13@4401.57,1067.29 ; v1(4388.78,1054.49) U34.L13@4401.57,1041.7 ; 4388.78,1080.09 U34.J13@4401.57,1092.88 ; 4388.78,1080.09 U34.K13@4401.57,1067.29 ; v1(4388.78,1105.68) U34.H13@4401.57,1118.47 ; v1(4388.78,1105.68) U34.J13@4401.57,1092.88 ; 4388.78,1131.27 U34.G13@4401.57,1144.06 v2(4414.37,1131.27) ; 4388.78,1131.27 U34.H13@4401.57,1118.47 ; U34.N13@4401.57,990.52 4414.37,1003.31 ; U34.N13@4401.57,990.52 v2(4414.37,977.72) ; U34.M13@4401.57,1016.11 v2(4414.37,1028.9) ; U34.M13@4401.57,1016.11 4414.37,1003.31 ; U34.L13@4401.57,1041.7 4414.37,1054.5 ; U34.L13@4401.57,1041.7 v2(4414.37,1028.9) ; U34.K13@4401.57,1067.29 v2(4414.37,1080.09) ; U34.K13@4401.57,1067.29 4414.37,1054.5 ; U34.J13@4401.57,1092.88 4414.37,1105.68 ; U34.J13@4401.57,1092.88 v2(4414.37,1080.09) ; U34.H13@4401.57,1118.47 v2(4414.37,1131.27) ; U34.H13@4401.57,1118.47 4414.37,1105.68 ; v2(4414.37,977.72) U34.N14@4427.16,990.52 4414.37,1003.31 ; 4414.37,1003.31 U34.M14@4427.16,1016.11 v2(4414.37,1028.9) ; v2(4414.37,1028.9) U34.L14@4427.16,1041.7 4414.37,1054.49 ; 4414.37,1054.5 U34.K14@4427.16,1067.29 v2(4414.37,1080.09) ; v2(4414.37,1080.09) U34.J14@4427.16,1092.88 4414.37,1105.68 ; 4414.37,1105.68 U34.H14@4427.16,1118.47 v2(4414.37,1131.27)
  Top Layer w14: 2138.73,442.95 v1(2200.65,442.95) 2202.63,440.96 C46.1@2231.35,440.96 2235.24,437.07 C48.2@2280.72,437.07 2308.67,437.07 v1(2314.55,442.95)
  Top Layer w15: R13.1@627.02,84.45 627.08,84.39 627.08,50.97 v1(627.14,50.91) ; C27.2@1017.44,330 1049.22,330 v1(1049.4,330.18) ; C32.1@1536.5,1119.73 v1(1576.68,1119.73) ; v1(1537.64,1012.4) C33.1@1537.64,1043.59 ; v1(1776.86,883.47) 1777.47,882.86 C42.1@1809.5,882.86 ; v1(1903.16,657.22) 1903.73,657.79 1921.55,657.79 D7.1@1929,665.25 ; v1(3265.34,1204.75) U27.3@3265.34,1263.93 ; R101.1@3542.1,1183.71 3569.93,1183.71 v1(3577.77,1191.54)
  Top Layer w20: v1(80.09,231.18) J25.B1@109.7,231.18 ; v1(80.09,471.33) J25.B12@109.7,471.33 ; v1(910.24,2000) SW2.3@910.24,2035.35
  Bottom Layer w5.3: v1(488.92,2041.18) 499.9,2030.2 U64.2@519.68,2030.2 ; v1(2643.73,613.01) v1@2643.82,612.93
  Bottom Layer w6: U61.10@2249.13,1036.65 2249.13,1009.39 2254.13,1004.38 2259.75,1004.38 2260.42,1003.71 v1(2265.29,1003.71) ; U61.11@2264.88,1036.65 2264.88,1004.64 v1@2265.29,1004.22
  Bottom Layer w7: U59.9@2643.82,584.08 v1@2643.82,612.93
  Bottom Layer w8: v1(4065.95,1544.8) 4065.95,1566.11 C231.1@4066.18,1566.34
  Bottom Layer w10: U65.3@306.02,497.27 U65.8@338.89,497.27 395.31,497.27 411.06,481.52 v1(504.73,481.52) ; v1(2380.17,565.14) 2382.34,565.14 2386.13,568.93 R363.2@2417.61,568.93 ; R354.2@2774.92,555.71 2776.95,553.67 2805.43,553.67 v1(2806.96,552.14) ; R351.1@2870.22,709.71 2871.54,711.03 v1(2895.94,711.03) 2897.26,709.71 C255.2@2920.33,709.71 ; U58.2@2895.63,516.32 2895.63,475.37 v1(2911,460) ; C254.2@3131.12,338.39 3137.13,344.4 3184.08,344.4 3199.7,360.02 C250.2@3201.47,360.02 ; C252.2@3197.08,260.33 3198.33,259.08 3198.33,240.09 v1(3199.57,238.84) ; C246.2@3407.4,1008.52 3407.4,970.72 3411.07,967.05 v1(3411.07,964.88) ; C245.2@3473.79,467.26 3511.79,467.26 C243.1@3523.11,478.58 ; C244.2@3528.09,329.52 v1@3565.84,329.52 ; J11.9@3654.17,1800 3662.25,1800 3682.69,1820.45 C239.2@3718.88,1820.45 ; C240.1@3655.94,1038.16 3665.57,1028.53 3682.47,1028.53 v1(3684,1027) ; C238.1@3783.09,542.75 3784.39,541.45 3801.49,541.45 v1(3802.8,540.15) ; C237.2@3785.48,248.08 3792.57,248.08 3809.5,231.15 v1(3811.06,231.15) ; U57.8@3794.57,327.04 3794.57,309.83 3794.57,307.16 3797.23,304.51 v1(3797.84,304.51) ; U56.8@3797.44,33.83 v1(3820.84,33.83) ; C233.1@3989.3,509.32 3989.3,495.39 v1(4012.8,471.9) ; v1(4114.27,687.38) 4115.22,686.43 C224.2@4146.07,686.43 ; v1(4138.31,767.58) 4137.5,768.39 4137.5,783.44 4170.8,816.74 C219.2@4184.4,816.74 C220.2@4184.4,842.29 4184.4,861.35 v1(4182.82,862.93) ; C225.2@4171.17,1049.46 4185.07,1049.46 v1(4189.47,1053.85) ; C223.2@4179.24,1108.74 4189.37,1108.74 v1(4195.57,1114.94) ; C222.2@4182.37,1169.07 4186.07,1169.07 4195.48,1178.48 v1(4209.64,1178.48) ; C221.2@4207.64,1201.42 4214.34,1201.42 v1(4224.03,1191.72) ; v1(4209.6,641.33) 4220.43,652.16 C202.2@4254,652.16 ; v1(4213.08,698.1) 4216.71,701.73 C205.2@4276.47,701.73 ; C211.2@4232.91,1207.76 4233.58,1207.76 4245.11,1219.29 v1(4245.78,1219.29) ; C216.2@4233.88,1025.59 4255.34,1025.59 4258.66,1028.9 v2(4260.82,1028.9) ; C215.2@4235.05,1148.05 4251.83,1131.27 v2(4260.82,1131.27) ; C214.2@4239.33,961.7 4239.1,961.93 4239.1,971.87 4243.43,976.19 4259.29,976.19 v2(4260.82,977.72) ; C213.2@4241.32,1054.3 4241.42,1054.4 v1@4286.41,1054.4 ; C217.1@4244.5,1105.54 4244.64,1105.68 v1(4286.41,1105.68) ; v1(4247.81,772.59) 4247.81,749.71 4254.18,743.33 4279.42,743.33 C206.1@4280.06,742.7 ; C207.2@4289.05,928.01 4289.05,928.94 v1(4310.96,950.85) ; C210.2@4290.3,849.86 4290.3,890.19 C204.2@4290.48,890.38 ; C209.2@4290.86,954.4 4290.86,966.62 4301.96,977.72 v2(4312.01,977.72) ; C208.1@4300.57,1144.08 4300.57,1142.7 4310.47,1132.8 v2(4312.01,1131.27) ; C203.2@4317.65,1192.22 4324.48,1192.22 v1(4334.68,1202.43) ; C201.2@4335.28,954.98 4335.28,1000.99 v1(4337.6,1003.31) ; v1(4337.6,1105.68) 4340.5,1108.58 C200.2@4340.5,1147.88 ; v1(4341.16,1399.74) 4341.29,1399.61 4364.88,1399.61 C189.1@4365.57,1399.48 4366.55,1398.51 C188.1@4366.55,1339.92 4366.55,1311.11 4387.13,1290.53 C191.2@4387.13,1282.19 4387.13,1257.09 C190.2@4387.58,1256.63 4386.4,1255.45 4386.4,1244.5 4375.5,1233.6 4375.5,1227.31 v1(4373.97,1225.78) 4373.48,1225.29 C192.2@4373.48,1209.55 ; C198.1@4353.6,1651.01 v1(4381.29,1650.98) ; v1(4363.19,954.32) 4363.19,952.16 4365.91,949.44 4365.91,943.08 C197.2@4369.18,939.81 ; v2(4363.19,1131.27) 4375.12,1143.2 C196.1@4377.67,1143.2 ; v1(4388.78,1003.31) 4393.64,998.45 C182.1@4428.78,998.45 4428.78,999.43 C182.1@4427.87,1000.34 ; v1@4388.78,1054.92 4430.46,1054.92 C179.2@4430.89,1055.34 ; v1(4388.78,1105.68) 4394.77,1111.67 C181.1@4429.33,1111.67 ; v2(4414.37,977.72) 4416.1,977.72 4427.05,966.77 C184.1@4427.05,965.79 ; v2(4414.37,1028.9) 4414.37,1026.78 4423.61,1017.54 C185.1@4423.61,1016.26 ; v2(4414.37,1080.09) 4415.9,1081.62 4420.16,1081.62 4428.32,1089.77 C183.1@4428.32,1090.76 ; v1(4415.65,951.09) 4417.18,949.56 4424.12,949.56 4431.7,941.99 C186.2@4431.7,941.2 ; v1(4455.5,923.12) 4456.16,923.78 4471.7,923.78 C175.2@4472.36,924.43 ; R314.1@4461.48,569.28 4461.48,571.25 4474.33,584.1 v1(4474.33,586.05) 4474.33,588.22 4465.62,596.92 C178.1@4465.62,608.97 ; v1(4471.45,995.6) 4471.8,995.25 4489.19,995.25 C176.2@4489.53,994.91 ; C174.2@4472.48,1106.41 4473.27,1107.19 4473.27,1121.07 v1(4474.05,1121.85) ; C172.2@4513.34,1060.66 4523.19,1070.51 v1(4529.28,1070.51) ; C173.2@4516.93,1165.76 4524.49,1173.32 v1(4531.32,1173.32) ; C171.2@4524.73,861.53 4544.95,861.53 4564.22,842.27 C168.2@4564.22,814.75 ; C170.1@4535.13,612.65 v1(4552.14,595.64) ; C167.1@4630.84,627.24 4630.84,608.48 v1(4637.38,601.94) ; C165.1@4675.75,953.13 4702.53,953.13 4718.61,969.2 C162.1@4738.43,969.2 v1(4738.43,942.93) ; C164.1@4711.73,633.99 4711.73,611.84 4720.65,602.91 v1(4749.38,602.91) 4758.03,594.26 R308.1@4758.03,573.48 ; v1(4726.83,1525.28) 4727.94,1525.28 4736.68,1534.02 4746.57,1534.02 C160.1@4753,1540.45 ; C163.1@4728.94,1637.41 4728.94,1605.83 4753,1581.78 C160.1@4753,1540.83 ; v1(4794.56,855.91) 4796.73,855.91 4800.14,859.33 C159.2@4838.74,859.33 ; v1(4838.74,814.75) 4868.92,844.93 C158.1@4891.38,844.93 ; v1(5005.98,1538.06) R302.2@5039.74,1538.08 ; R303.2@5017.69,1755.06 5059.85,1755.06 v1(5105.92,1801.13) ; v1(5115.64,1015.56) C156.2@5115.64,1040.23 ; v1(5175.93,1830.51) 5178.34,1832.92 C155.2@5178.34,1877.86 ; D17.2@5182.16,365.99 5183.68,367.5 5192.81,367.5 v1(5194.32,369.02) ; U53.11@5360.84,1270.93 5367.38,1270.93 5368.02,1270.28 5390.45,1270.28 5395.29,1265.44 v1(5395.29,1241.4) ; v1(5376.52,1789.73) C153.2@5376.52,1818.05 ; v1(5451.52,1540.83) C150.2@5451.52,1568.05 ; v1(5451.52,1789.73) C151.2@5451.52,1818.05 ; v1(5575.69,1539.4) C148.2@5575.69,1568.05 ; v1(5575.69,1789.73) C149.2@5575.69,1818.05 ; C147.2@5613.39,1364.56 5613.39,1410.11 v1(5618.64,1415.36) ; C146.1@5627.1,1176.44 5627.15,1176.39 v1(5627.15,1151.35) ; C144.2@5695.69,1568.05 5697.33,1566.41 v1(5728.81,1566.41) ; v1(5695.69,1789.73) C145.2@5695.69,1818.05 ; v1(5737.89,1207.4) R274.2@5737.89,1244.58 ; R267.2@5833.71,1248.51 5833.71,1212.07 v1(5833.9,1211.87) ; v1(6062.68,864.66) U51.B3@6082.37,884.34 ; v1(6101.18,1357.83) 6101.34,1358 6136.56,1358 C143.2@6136.89,1358.32 ; v1(6208.6,871.42) 6208.69,871.52 R253.1@6235.99,871.52 ; v1(6362,119.39) 6362,96.42 C141.2@6365.44,92.98 ; v1(6521.05,65) 6521.05,67.16 6526.63,72.75 6526.63,86.83 6531.47,91.67 R239.1@6532.69,91.67 ; R233.1@6736.85,1908.33 6736.85,1890.49 v1(6747.43,1879.92)
  Bottom Layer w11: R88.1@3121.91,1129.49 3121.91,1155.18 v1(3122.01,1155.28) ; v1(4454.04,1189.46) 4454.38,1189.12 C177.2@4482.22,1189.12 ; v1(5030.29,429.03) 5030.93,428.39 5055.93,428.39 C157.2@5056.57,427.75 ; v1(5712.39,879.22) 5712.09,878.91 5713.83,877.17 R195.1@5752.8,877.17
  Bottom Layer w12: v1(421.14,1884.01) Q6.3@421.14,1921.76 ; C266.1@644.26,2034.88 644.26,2006.1 657.93,1992.44 v1(689.76,1992.44) ; v1(708.51,543.88) C264.2@770.02,543.88 v1(828.6,543.88) ; U62.3@1030.59,1949.33 1030.59,1904.06 1032.23,1902.41 v1(1032.23,1900.79) ; Q4.3@1226.13,2002.26 v1(1257.62,2002.26) ; R374.1@1581.16,1687.95 1581.16,1708.76 1592.04,1719.64 1659.13,1719.64 v1@1672.38,1706.38 ; U60.3@2278.46,1304.51 2307.55,1304.51 v1(2322.76,1289.3) ; C257.1@2304.62,875.72 2332.42,875.72 v1(2332.6,875.54) ; C256.1@2435.4,1170.68 v1(2470.62,1170.68) ; C253.2@3210.86,1058.16 3229.18,1058.16 v1(3238.72,1048.62) ; C242.2@3542.05,280.85 3559.68,280.85 v1(3561.2,279.33) ; C236.2@3920,970 3921.4,968.6 3921.4,943.76 v1(3949.56,915.6) 3970.31,936.35 C234.1@3988.32,936.35 4014.32,962.34 C230.2@4072.96,962.34 ; v1(3937.57,1165.74) 3950.51,1178.68 C235.1@3979.56,1178.68 3979.84,1178.97 C232.1@4050.77,1178.97 4074.72,1178.97 4092.23,1161.46 C229.1@4106.03,1161.46 ; R323.1@3943.1,795.59 3979.57,795.59 v1(4035.17,739.99) ; v1@4068.6,723.02 4082.16,736.58 4094.31,736.58 C228.1@4103.27,745.54 ; v1(4114.93,849.12) 4114.93,850.75 4118.76,854.57 4118.76,869.49 4119.23,869.96 4119.23,881.39 C227.2@4121.49,883.65 ; C226.2@4156.26,844.93 4180.96,844.93 4183.61,842.29 C220.2@4184.4,842.29 ; C218.2@4225.04,910.86 4225.83,910.86 4228.1,913.13 4228.1,922.11 4231.18,925.19 v1(4231.18,926.81) ; v1(4336.23,613.95) 4337.37,612.8 4346.88,612.8 4354.29,605.4 4374.02,605.4 C195.1@4379.69,611.07 ; v2(4363.19,977.72) 4375.79,977.72 C193.2@4392.4,961.11 ; C194.1@4398.05,1145.32 4400.31,1145.32 v2(4414.37,1131.27) 4421.96,1138.86 C187.1@4429.67,1138.86 ; v1(4529.28,1070.51) 4540.62,1059.18 C169.2@4566.16,1059.18 ; C154.2@5191.31,616.25 5197.12,610.43 5197.12,595.33 5216.45,576 v1(5254,576) ; v1(5929.42,968.97) 5935.3,963.08 U51.E5@5964.26,963.08 ; R264.1@5960.46,395.65 v1(5960.46,418.23) ; U51.C1@6043,805.6 6043.26,805.34 6043.26,800.01 6047.28,795.99 6047.28,781.8 v1(6046.78,781.31) ; U52.2@6168.23,270.51 6193.69,270.51 6200.58,277.4 v1(6254.09,277.4) ; R246.2@6351.89,1675 6355.83,1675 6361.64,1669.19 6361.64,1659.63 6371.67,1649.6 v1(6371.94,1649.6) ; v1(6621.44,1879.92) 6621.44,1905.95 6634.66,1919.17 R236.2@6655.79,1919.17 ; v1(6703.69,-47.64) 6705.38,-45.94 R235.2@6705.38,-2.31 ; R231.2@6807.81,-41.48 6835.96,-41.48 6841.79,-47.3 v1(6843.41,-47.3)
  Bottom Layer w15: C258.1@2244.62,875.72 C257.1@2304.62,875.72
  Bottom Layer w20: v1(1042.72,2064.5) Q5.3@1042.72,2102.05 ; v1(2440.44,1211.97) R362.1@2440.44,1245.68 ; C168.2@4564.22,814.75 4605.31,814.75 v1(4615.01,805.06)
  other v1: 319,-115 419,-115 519,-115 619,-115 719,-115 819,-115 919,-115 1019,-115 1119,-115 1219,-115 1319,-115 1419,-115 1519,-115 1619,-115 1719,-115 1819,-115 1919,-115 2019,-115 2119,-115 2219,-115 5276,-115 5376,-115 5476,-115 5576,-115 5676,-115 5776,-115 5876,-115 5976,-115 6076,-115 6176,-115 6276,-115 6838,-113 6938,-113 7218,-110 3160,-109 6483.89,-87.19 668,-60 768,-60 868,-60 968,-60 1068,-60 1168,-60 1366,-59 1466,-59 1566,-59 1666,-59 1766,-59 1866,-59 1966,-59 2066,-59 2166,-59 2266,-59 2366,-59 423.01,-47.42 451.67,-47.42 480.33,-47.42 509,-47.42 537.66,-47.42 3271.11,-35.02 3318.12,-33.99 3364,-34 3411.04,-33.97 3456.32,-34.14 3497.69,-33.04 3556.6,-32.52 3225.65,-31.4 423.01,-18.76 451.67,-18.76 480.33,-18.76 509,-18.76 537.66,-18.76 6843.41,-12.15 6867.77,32.51 7515,121 7459,168 960.37,178.53 6113.11,220.31 7515,221 408.56,246.92 6090.47,257.71 6135.75,257.71 7459,268 408.56,275.59 434.84,276.57 3069.65,284.74 3093.54,284.74 448.04,304.9 476.71,304.9 7515,321 2882.7,333.2 2916.35,333.2 2952.99,332.7 448.04,333.56 476.71,333.56 3068.61,340.68 3092.5,340.68 1614.73,342.34 3371.74,351.17 3392.98,351.45 7295.19,356.43 448.04,362.23 476.71,362.23 7459,368 5460,372 2895.9,373.18 2929.28,372.56 2861.3,373.59 5374,375 5311,376 3340.16,378.98 3371.74,378.98 3392.98,379.26 5740,387 448.04,390.89 476.71,390.89 3340.16,406.79 3371.74,406.79 3392.98,407.07 1616.72,415.33 7515,421 3985.24,434.49 4040.36,434.49 7459,468 2134.1,488.78 7515,521 1567.18,531.07 1617.18,531.07 1717.18,530.69 1517.85,532.07 1665.57,532.27 3556.8,549.41 3519.81,549.92 7459,568 1417.18,573.29 1467.18,573.29 1517.18,573.29 1567.18,573.29 1617.18,573.29 1667.18,573.29 1717.18,573.29 4071.44,574.49 3520.14,579.08 3555.85,579.08 3358.61,598.24 4131.35,612.37 3387.01,614.43 7515,621 4036.63,628.91 3385.12,654.13 7459,668 5922.58,668.82 6569.88,669.39 5861,678 5328.08,697.84 2517.39,703.45 7515,721 5914,731 3471.83,732 2479.99,740.85 2517.39,740.85 5297.57,743.9 5328.08,743.9 5358.59,743.9 7459,768 3495.83,787 5297.57,789.97 5328.08,789.97 5358.59,789.97 3543.83,795 7223.87,807.38 6140,813 7515,821 2997.83,833 5297.57,836.03 5328.08,836.03 5358.59,836.03 7459,868 2992.83,871 6946,880 5297.57,882.09 5328.08,882.09 5358.59,882.09 3172.83,884 7515,921 5297.57,928.16 5328.08,928.16 5358.59,928.16 2923.83,934 3551.58,933.89 3056.83,943 6396,967 7459,968 5328.08,974.22 6024,985 1790.43,1020.84 1827.83,1020.84 7515,1021 5884,1022 5929,1023 6389,1048 5905,1052 1790.43,1058.24 1827.83,1058.24 7459,1068 1356,1075 3319.76,1117.29 7515,1121 6952,1154 7459,1168 5445.49,1210.89 5784,1211 3332.07,1216.58 7515,1221 5495.68,1241.4 7459,1268 5445.49,1271.91 7515,1321 6720,1337 5189.82,1367.51 5227.22,1367.51 7459,1368 1360,1376 5189.82,1404.91 7515,1421 5904.59,1450.59 5853.27,1451.73 2380,1460 3816.08,1464.79 7459,1468 4073,1471 6516,1502 3785.57,1510.85 3816.08,1510.85 3846.59,1510.85 2998.97,1518.56 7515,1521 3484.65,1522.69 6281,1538 2379,1546 2948.77,1549.07 3049.17,1549.07 3434.46,1553.2 3534.85,1553.2 3785.57,1556.91 3816.08,1556.91 3846.59,1556.91 7459,1568 5416.82,1569.33 2998.97,1579.58 3484.65,1583.71 3785.57,1602.98 3816.08,1602.98 3846.59,1602.98 7515,1621 3785.57,1649.04 3816.08,1649.04 3846.59,1649.04 7459,1668 3785.57,1695.1 3816.08,1695.1 3846.59,1695.1 7515,1721 3816.08,1741.16 6305,1762 6519,1768 7459,1768 -109,1797 7515,1821 6689,1834 7457,1861 6460.16,1871.6 6418.5,1875.1 -107,1890 6968.01,1907.59 6422.74,1913.01 6968.01,1949.02 6893,1962 6968.01,1987.22 831,2000 2859,2017 3208,2051 6059,2058 779,2072 2821,2098 4916.62,2098.46 1691,2099 1831,2102 1986,2103 2142,2104 2281,2107 2421,2108 3266,2109 4611,2109 4711,2109 4811,2109 5011,2109 5111,2109 5211,2109 5311,2109 5411,2109 5511,2109 5611,2109 5711,2109 5811,2109 5911,2109 6011,2109 6111,2109 6311,2109 145,2110 2565,2110 2640,2111 3151,2111 6979.72,2110.52 2723,2112
  other v3: 3748.23,102.73 3787.6,102.73 3748.23,142.1 3787.6,142.1 3745.36,395.94 3784.73,395.94 3745.36,435.31 3784.73,435.31
GND_XDS: C2.2 C3.1 C6.1 C7.1 C9.2 C10.1 C14.2 C16.1 C17.1 C18.2 C19.2 C21.2 C23.1 C24.2 C25.2 C28.2 C29.1 C30.1 C259.2 C260.1 C261.2 C262.1 C263.1 C264.1 C265.1 C267.1 C268.1 C269.1 C270.2 C271.1 D1.1 D19.1 DS1.1 J24.5 R10.1 R19.2 R22.2 R23.2 R24.2 R402.1 R414.1 R416.2 TP3.1 TP13.1 U1.3@121.44,1088.92 U1.8@88.56,1088.92 U2.2 U3.5 U4.6 U4.9@318.69,848.32 U5.4 U7.3 U7.4 U9.8 U11.4 U12.5 U13.5 U63.10 U63.17 U63.48 U63.55 U63.58 U63.64 U63.66 U63.80 U63.114 Y4.2 Y4.4 | length 3377.3
  Top Layer w8: J24.5@11.81,1123.37 58.68,1123.37 v1(58.94,1123.11) v1@60,1123.11
  Top Layer w12: v1(-96.98,1641.17) DS1.1@-58.48,1641.17 ; v1(-94.03,1567.07) D1.1@-55.53,1567.07 ; U1.8@88.56,1088.92 U1.3@121.44,1088.92 136.77,1088.92 v1@175,1127.15 ; U2.2@154.1,1332 154.1,1370.01 v1(155,1370.91) ; U3.5@164.01,1632.55 v1(164,1678) ; v1(174.9,1129.75) v1@175,1129.65 ; C2.2@202.83,835.89 202.83,861.2 216.63,875 245,875 ; v1(231.43,1558.65) C3.1@267.59,1558.65 ; v1(274.55,1355.66) C6.1@306.88,1355.66 ; v1(291.26,1020) 309.73,1038.47 C7.1@321.69,1038.47 ; U4.9@318.69,848.32 331.48,861.12 U4.6@331.48,903.44 ; v1(395,826.17) 404.72,835.89 C10.1@427.56,835.89 ; C9.2@411.06,1680.54 v1(444.71,1680.54) ; C14.2@510,905.9 v1@510,933.82 ; R10.1@541.97,1090.79 v1(541.97,1124.26) ; TP3.1@598.48,1010.35 v1(598.48,1043.83) ; C17.1@637.63,847.6 v1(663.07,822.16) ; v1(641.82,1573.46) U5.4@641.82,1634.52 ; C16.1@648.6,791.85 648.79,792.03 684.53,792.03 v1(690.5,798) ; C18.2@700.81,1497.63 v1(700.81,1526.55) ; C19.2@708.51,1667.2 740.33,1667.2 v1(740.37,1667.24) ; v1(815,1415.6) R19.2@815,1480.31 ; v1(827.49,824.51) C21.2@827.49,859.58 ; v1(866.99,1429.87) R22.2@866.99,1480.31 ; U7.3@877.09,1632.31 v1(877.09,1676.14) ; U7.4@927.09,1632.31 v1(927.09,1676.14) ; R23.2@945.89,1480.31 v1(945.89,1453.83) 948.65,1451.07 C24.2@948.65,1414.53 ; C25.2@969,1129.78 989.01,1129.78 998.58,1120.21 v1@998.83,1120.21 ; C23.1@978.62,1071.57 1000.33,1071.57 1008.9,1080.14 v1(1008.9,1090.98) ; R24.2@1007.5,1592.18 1007.5,1622.08 v1(1007.93,1622.51) ; v1(1074.64,729.43) 1076.26,729.43 1079.86,733.03 C28.2@1105.58,733.03 ; v1(1079.12,796.57) TP13.1@1079.12,824.22 ; v1(1100.09,1197.99) 1111.83,1197.99 1122.11,1187.72 C30.1@1122.11,1166.11 ; U9.8@1118.64,1337.95 v1(1241.03,1337.95) ; v1(1122.11,962.95) C29.1@1122.11,998.3 ; U11.4@1191.5,893.59 v1(1237.41,893.59) ; U13.5@1191.73,1269.73 v1(1237.64,1269.73) ; U12.5@1193.7,833.03 v1(1193.7,863.35)
  Bottom Layer w7: v1@294.89,1182.24 U63.17@342.35,1182.24 ; U63.10@342.35,1072.01 v1@389.81,1072.01 ; 621.88,836.47 U63.114@621.88,871.22 ; U63.48@637.63,1477.52 637.63,1511.88 ; v1@747.86,1430.06 U63.55@747.86,1477.52 ; 795.11,1435.49 U63.58@795.11,1477.52 ; v1(870.44,1181.03) 871.66,1182.24 U63.80@948.65,1182.24 ; U63.64@889.59,1477.52 922.2,1477.52 ; v1@901.19,1402.72 U63.66@948.65,1402.72
  Bottom Layer w8: v1(294.7,1182.06) v1@294.89,1182.24 ; v1@389.81,1072.01 395,1077.2 v1(395,1078.07) ; 621.88,836.47 636.19,822.16 v1(663.07,822.16) ; 637.63,1511.88 652.3,1526.55 v1(700.81,1526.55) ; v1@747.86,1430.06 v1(748.05,1429.87) ; 795.11,1435.49 797.94,1432.66 v1(815,1415.6) ; v1(901,1402.53) v1@901.19,1402.72 ; 922.2,1477.52 v1(945.89,1453.83)
  Bottom Layer w12: v1(174.9,1129.75) 176.3,1129.75 205,1101.05 C269.1@205,1097.11 205,1094.98 210.81,1089.17 R414.1@251.47,1089.17 ; C268.1@210.82,1217.4 261.88,1217.4 C267.1@265.82,1213.46 ; v1(243.98,959.49) 243.98,894.63 224.15,874.79 C270.2@175,874.79 176.08,875.88 176.08,958.64 210.55,993.11 v1(245,993.11) ; C267.1@265.82,1217.4 v1(265.82,1248.11) ; C265.1@648.6,791.85 654.75,798 v1(690.5,798) ; v1(708.51,709.23) C264.1@770.02,709.23 v1(828.6,709.23) ; v1(742.1,1536.63) R402.1@742.1,1563.62 ; C262.1@1042.72,967.71 1068.91,967.71 1073.67,962.95 v1(1122.11,962.95) 1157.04,962.95 1168.63,974.54 Y4.2@1168.63,1011.01 ; C263.1@1042.72,1129.75 1060.91,1129.75 1073.64,1142.48 v1(1087.59,1142.48) 1105.64,1124.44 Y4.4@1105.64,1097.63 ; C261.2@1064.12,1197.99 v1(1100.09,1197.99) ; v1(1079.12,796.57) C260.1@1079.12,824.22 ; C259.2@1142.27,1687.95 1175.93,1687.95 v1(1177.39,1689.4)
  other v1: 318.69,825.68 281.29,848.32 356.09,848.32 318.69,870.96 510.2,934.01 999.04,1120 -100.21,1451.4 -50.21,1451.4 -100.21,1501.4 -50.21,1501.4
GPIO_2/CLKOUT: J21.48 | length 54.2
  Top Layer w5.3: J21.48@6751.27,91.39 6751.27,124.69 6765.52,138.94 v1(6766.31,138.94)
GPIO_2/CLKOUT1: J23.48
HR_MCAN0_RX: R252.1 U35.2 | length 4014.3
  Top Layer w5.3: U35.2@4417.57,1631.32 4451.17,1631.32 v1(4459.53,1639.69)
  SIG 1 w4.75: v1(4459.53,1639.69) 4459.53,1550.47 4498.8,1511.2 4498.8,1477.64 4534.19,1442.25 4575.44,1442.25 4589.74,1427.95 4636.95,1427.95 4646.32,1437.32 4690.92,1437.32 4800.51,1327.74 4800.51,1258.88 4828.54,1230.85 4889.38,1230.85 4903.33,1216.9 4989.94,1216.9 5011.86,1238.82 5191.98,1238.82 5264.66,1311.5 5556.19,1311.5 5567.82,1299.87 5965.63,1299.87 5991.76,1326.01 6346.75,1326.01 6766.07,906.69 6766.07,567.84 6689.48,491.24 6405.05,491.24 6331.59,417.78 6331.59,377.19 6305.36,350.96 6280.37,350.96 6275.64,346.23 6275.36,346.23 6266.97,337.84 6266.97,294.13 6289.28,271.83 6289.28,263.28 v1(6291.66,260.9)
  Bottom Layer w5.3: R252.1@6245,185.71 6247.22,187.94 6247.22,200.4 6291.66,244.84 v1(6291.66,260.9)
HR_MCAN0_TX: R251.1 U35.4 | length 3881.8
  Top Layer w5.3: U35.4@4417.57,1670.69 v1(4455.49,1670.69)
  SIG 1 w4.75: v1(4455.49,1670.69) 4456.6,1669.59 4467.69,1669.59 4585.85,1551.43 4585.85,1445.64 4593.78,1437.7 4632.62,1437.7 4643.96,1449.04 4698.92,1449.04 4810.56,1337.41 4810.56,1263.04 4832.7,1240.9 4935.31,1240.9 4951.92,1257.51 5141.24,1257.51 5150.18,1248.57 5187.94,1248.57 5260.63,1321.25 5560.23,1321.25 5571.86,1309.62 5954.36,1309.62 5982.22,1337.48 6351.97,1337.48 6780.6,908.85 6780.6,564.69 6696.83,480.92 6413.01,480.92 6356.33,424.25 6356.33,377.15 6308.58,329.4 v1(6287.3,329.4)
  Bottom Layer w5.3: R251.1@6260,332.71 6283.99,332.71 v1(6287.3,329.4)
I2C0_SCL/PR1_PRU1_GPIO10: J1/J3.9 U57.12 | length 2666.4
  Bottom Layer w5.3: J1/J3.9@2254.17,100 2304.25,150.07 2375.75,150.07 2402.76,177.08 2402.76,310.07 2426.38,333.69 2426.38,334.65 2659.46,334.65 2730.23,405.42 2944.36,405.42 2947.54,402.23 2984.18,365.6 2984.18,255.2 3134.32,105.05 3315.11,105.05 3345.36,135.3 3468.7,135.3 3534,70 3534,-39.39 3556.83,-62.21 3750.62,-62.21 3758.1,-54.74 3758.1,-31.56 3748.99,-22.45 3736.05,-22.45 3637.33,76.27 3637.33,226.76 3619.77,244.31 3619.77,342.1 3598.43,363.45 3598.43,379.75 3611.05,392.38 3643.32,392.38 3656.73,405.78 U57.12@3686.31,405.78
I2C0_SDA/PR1_PRU1_GPIO0: J1/J3.10 U57.9 | length 2501.5
  Bottom Layer w5.3: J1/J3.10@2354.17,100 2418.09,163.92 2418.09,307.32 2433.83,323.06 2674.08,323.06 2746.14,395.12 2940.09,395.12 2972.98,362.23 2971.91,252.9 3134.04,90.77 3315.4,90.77 3349.62,125 3457,125 3522,60 3522,-45.58 3549.41,-72.99 3761.78,-72.99 3771.76,-63.02 3771.76,-22.87 3758.41,-9.52 3738.36,-9.52 3647.63,81.22 3647.63,279.98 3667.84,300.19 3727.07,300.19 3735.52,308.64 U57.9@3735.52,327.04
I2C1_SCL/GPIO137: J5/J7.49 U41.10 | length 5357.3
  Top Layer w5.3: U41.10@5066.55,1934.2 5066.55,1973.61 5048.04,1992.12 5048.04,2048.58 5066.96,2067.5 5893.63,2067.5 6142.22,1818.91 6142.22,1426.42 6351.45,1217.2 6494.54,1217.2 6789.21,922.53 6789.21,562.7 6716.99,490.48 6576.65,490.48 6544.99,522.14 6371.57,522.14 6271.63,422.21 6239.49,422.21 6202.35,385.07 6098.52,385.07 5999.26,285.81 5999.26,179.79 5931.76,112.3 v1(5788.37,112.3)
  Bottom Layer w5.3: J5/J7.49@4754.17,100 4876.62,-22.45 5267.48,-22.45 5409.25,119.33 5777.9,119.33 5784.93,112.3 v1(5788.37,112.3)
